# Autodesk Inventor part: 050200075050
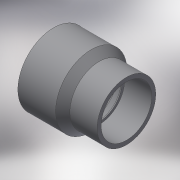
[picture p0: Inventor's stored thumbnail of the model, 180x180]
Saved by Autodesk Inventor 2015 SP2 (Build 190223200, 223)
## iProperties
Created: 2017-10
Part Number: 050200075050
Material: Generic
Description: PLASSON REDUCING SOCKET M.F.75(63)50 CEMENTED
Document SubType Name: Modeling
Designer: KIM
Density: 1 g/cm^3
Appearance: Default
Author: KIM
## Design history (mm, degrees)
derived "050200.ipt"
feature "Solid1::050200.ipt"
tag "TaggingFeature1"
body "Solid1"
other parameters: "d0" = 92, "d1" = 44, "d2" = 42, "d3" = 41, "d5" = 61, "d6" = 63, "d7" = 75, "d8" = 45, "d9" = 8.6217, "d12" = 0.63, "d_" = 63, "L_" = 44, "l_" = 41, "l_1" = 42, "E_" = 61, "H_" = 92, "D_" = 75, "d11" = 8.6217
